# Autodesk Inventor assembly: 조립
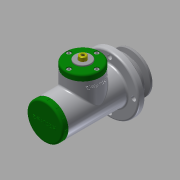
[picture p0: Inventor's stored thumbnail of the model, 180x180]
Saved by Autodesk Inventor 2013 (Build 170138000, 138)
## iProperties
Created: 2016-08
Part Number: 조립
Document SubType Name: Assembly
Designer: Administrator
Author: Administrator
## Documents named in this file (25)
- C:\Users\Administrator\Desktop\460808V1008\조립.iam
- C:\Users\Administrator\Desktop\460808V1008\본체.ipt
- C:\Users\Administrator\Desktop\460808V1008\V-벨트풀리.ipt
- C:\Users\Administrator\Desktop\460808V1008\너트 M10.ipt
- C:\Users\Administrator\Desktop\460808V1008\링크.ipt
- C:\Users\Administrator\Desktop\460808V1008\멈춤링 15 x 1.ipt
- C:\Users\Administrator\Desktop\460808V1008\멈춤링 35x1.6.ipt
- C:\Users\Administrator\Desktop\460808V1008\베어링 15 x 35 x 11.ipt
- C:\Users\Administrator\Desktop\460808V1008\볼트 M4 x 10.ipt
- C:\Users\Administrator\Desktop\460808V1008\볼트 M4 x 12.ipt
- C:\Users\Administrator\Desktop\460808V1008\부시1.ipt
- C:\Users\Administrator\Desktop\460808V1008\부시2.ipt
- C:\Users\Administrator\Desktop\460808V1008\분할핀 1.6 x 12.ipt
- C:\Users\Administrator\Desktop\460808V1008\사이드 커버.ipt
- 사이드 커버.ipt
- C:\Users\Administrator\Desktop\460808V1008\슬라이더.ipt
- C:\Users\Administrator\Desktop\460808V1008\오일 실 15 25 7.ipt
- C:\Users\Administrator\Desktop\460808V1008\와셔 4x16.ipt
- C:\Users\Administrator\Desktop\460808V1008\와셔 10x21.ipt
- C:\Users\Administrator\Desktop\460808V1008\클래스터 핀 6 x 24.ipt
- C:\Users\Administrator\Desktop\460808V1008\키 4 x 4 x 18.ipt
- C:\Users\Administrator\Desktop\460808V1008\탑 부시.ipt
- C:\Users\Administrator\Desktop\460808V1008\탑 커버.ipt
- 탑 커버.ipt
- C:\Users\Administrator\Desktop\460808V1008\편심축.ipt
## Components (6 placed, 3 different names)
1. V-벨트풀리:1
2. ISO 4017 M4 x 10:1 — 각도:7
3. ISO 4762 M4 x 12:1 — 각도:8
4. ISO 4762 M4 x 12:2
5. ISO 4762 M4 x 12:3
6. ISO 4762 M4 x 12:4
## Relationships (2: Angle 2)
- 각도:7 [Angle]: ISO 4017 M4 x 10:1
- 각도:8 [Angle]: ISO 4762 M4 x 12:1
